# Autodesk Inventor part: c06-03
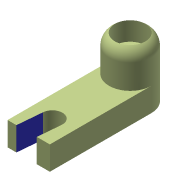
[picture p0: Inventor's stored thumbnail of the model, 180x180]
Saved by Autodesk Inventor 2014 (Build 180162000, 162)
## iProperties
Created: 2013-03
Part Number: c06-03
Material: Aluminum 6061
Document SubType Name: Modeling
Designer: Thom Tremblay
Density: 2.71 g/cm^3
Appearance: Zinc Chromate 2
Author: Thom Tremblay
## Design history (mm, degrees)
sketch "Sketch1"
  geometry: L1 (0, -12.5)-(60, -12.5); L2 (60, -12.5)-(60, 12.5); L3 (60, 12.5)-(0, 12.5); L4 (0, 12.5)-(0, -12.5); 2 further points
  constraints: 8 end point, 2 parallel, 1 coincident, 1 horizontal, 1 midpoint, 1 perpendicular
  dimensions: "d1" = 25 distance of L2.end L1.end; "d2" = 60 distance of L2.end L3.end
extrude "Base" new body sketch "Sketch1" distance "d3" = 14; taper "d4" = 0 deg
sketch "Sketch2"
  geometry: C1 r 12.5 at (0, 0); 1 further point
  constraints: 1 centre point, 1 coincident
extrude "Boss" join sketch "Sketch2" distance "d5" = 35; taper "d6" = 0 deg
sketch "Sketch3"
  geometry: L1 (-60, 12.5)-(-60, -12.5) reference; L2 (-60, -6)-(-60, 6); L3 (-45.477, 5.977)-(-60, 7.248); L4 (-46.523, -5.977)-(-60, -4.798); L5 (-60, 7.248)-(-60, -4.798); A1 r 6 centre (-46, 0) between (-45.477, 5.977) and (-46.523, -5.977); 2 further points
  constraints: 8 end point, 3 midpoint, 2 point on circle, 2 point on line, 2 tangent, 1 centre point, 1 collinear, 1 horizontal alignment, 1 parallel
  dimensions: "d8" = 12 diameter of A1; "d20" = 20 dimension on A1 L1; "d27" = 85 deg angle of L1 L3
extrude "Slot" cut sketch "Sketch3" stored distance "d9" = 24; taper "d10" = 0 deg
hole "Hole1" diameter "d13" = 11; stored, may be unused: countersink angle "d17" = 90 deg, drill point angle "d19" = 118 deg; dims "d11" = 10, "d12" = 10, "d14" = 6, "d15" = 18, "d16" = 11, "d18" = 8
fillet "Fillet1" dims "d26" = 8
body "Solid1"
